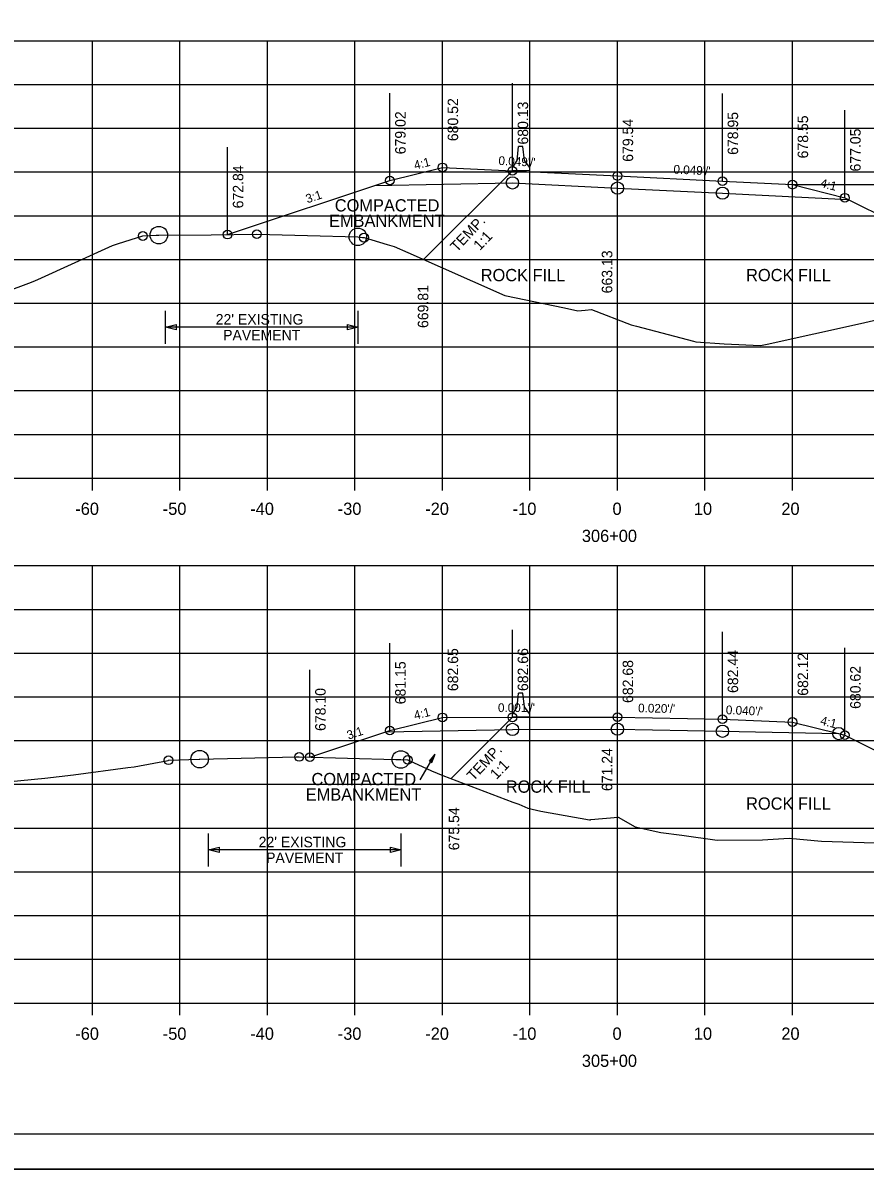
# Model space of a CAD drawing. Extents: x 1370515 to 1370849, y 383299 to 386073.
# Drawn here: x 1370609.9 to 1370706.1, y 384152.8 to 384283.8 of the extents above; entities that cross this region are included whole.
import ezdxf

# ---------------------------------------------------------------- set-up
doc = ezdxf.new("R2010")
doc.units = 0
for name, color, linetype in [('R_Alt Surface', 7, 'Continuous'), ('R_Axis', 7, 'Continuous'), ('R_Axis Annot', 7, 'Continuous'), ('R_Border', 7, 'Continuous'), ('R_Detour', 7, 'Continuous'), ('R_Exist Surface', 7, 'Continuous'), ('R_Fin Surface', 7, 'Continuous'), ('R_Grid', 7, 'Continuous'), ('R_No Plot', 7, 'Continuous'), ('R_ROW Annot', 7, 'Continuous'), ('R_Xsect Elev', 7, 'Continuous'), ('R_Xsect Slope', 7, 'Continuous')]:
    doc.layers.add(name, color=color, linetype=linetype)

msp = doc.modelspace()

# ---------------------------------------------------------------- linework, layer by layer
at = {"layer": 'R_Alt Surface'}
for points in [[(1370650.04, 384265.2), (1370665.8, 384265.51), (1370677.8, 384264.92), (1370689.8, 384264.33), (1370704.19, 384263.62)], [(1370651.34, 384202.76), (1370665.8, 384203.04), (1370677.8, 384203.06), (1370689.8, 384202.82), (1370703.09, 384202.56)]]:
    msp.add_lwpolyline(points, dxfattribs=at)
at = {"layer": 'R_Axis'}
for p, q in [((1370617.8, 384230.36), (1370617.8, 384233.16)), ((1370627.8, 384230.36), (1370627.8, 384233.16)), ((1370637.8, 384230.36), (1370637.8, 384233.16)), ((1370647.8, 384230.36), (1370647.8, 384233.16)), ((1370657.8, 384230.36), (1370657.8, 384233.16)), ((1370667.8, 384230.36), (1370667.8, 384233.16)), ((1370677.8, 384230.36), (1370677.8, 384233.16)), ((1370687.8, 384230.36), (1370687.8, 384233.16)), ((1370697.8, 384230.36), (1370697.8, 384233.16)), ((1370537.8, 384231.76), (1370817.8, 384231.76)), ((1370617.8, 384170.36), (1370617.8, 384173.16)), ((1370627.8, 384170.36), (1370627.8, 384173.16)), ((1370637.8, 384170.36), (1370637.8, 384173.16)), ((1370647.8, 384170.36), (1370647.8, 384173.16)), ((1370657.8, 384170.36), (1370657.8, 384173.16)), ((1370667.8, 384170.36), (1370667.8, 384173.16)), ((1370677.8, 384170.36), (1370677.8, 384173.16)), ((1370687.8, 384170.36), (1370687.8, 384173.16)), ((1370697.8, 384170.36), (1370697.8, 384173.16)), ((1370537.8, 384171.76), (1370817.8, 384171.76))]:
    msp.add_line(p, q, dxfattribs=at)
at = {"layer": 'R_Border'}
msp.add_line((1370843.98, 384156.76), (1370527.8, 384156.76), dxfattribs=at)
at = {"layer": 'R_Detour'}
for p, q in [((1370666.36, 384268.07), (1370666.5, 384269.65)), ((1370666.75, 384269.66), (1370666.5, 384269.65)), ((1370667, 384269.66), (1370666.75, 384269.66)), ((1370667.19, 384268.08), (1370667, 384269.66)), ((1370665.8, 384267.22), (1370666.36, 384268.07)), ((1370667.8, 384267.26), (1370667.19, 384268.08)), ((1370665.8, 384266.89), (1370655.65, 384256.74)), ((1370665.8, 384266.89), (1370665.8, 384267.22)), ((1370667.8, 384266.93), (1370665.8, 384266.89)), ((1370667.8, 384266.93), (1370667.8, 384267.26)), ((1370666.36, 384205.6), (1370666.5, 384207.18)), ((1370666.75, 384207.19), (1370666.5, 384207.18)), ((1370667, 384207.19), (1370666.75, 384207.19)), ((1370667.19, 384205.61), (1370667, 384207.19)), ((1370665.8, 384204.75), (1370666.36, 384205.6)), ((1370665.8, 384204.42), (1370665.8, 384204.75)), ((1370667.8, 384204.79), (1370667.19, 384205.61)), ((1370667.8, 384204.46), (1370667.8, 384204.79)), ((1370665.8, 384204.42), (1370658.79, 384197.41)), ((1370667.8, 384204.46), (1370665.8, 384204.42)), ((1370655.26, 384197.26), (1370656.97, 384200.19)), ((1370656.34, 384199.4), (1370656.97, 384200.19)), ((1370656.36, 384199.39), (1370656.89, 384200.04)), ((1370656.38, 384199.38), (1370656.8, 384199.9)), ((1370656.4, 384199.36), (1370656.72, 384199.75)), ((1370656.42, 384199.35), (1370656.63, 384199.61)), ((1370656.45, 384199.34), (1370656.55, 384199.46)), ((1370656.49, 384199.31), (1370656.55, 384199.46)), ((1370656.51, 384199.3), (1370656.63, 384199.61)), ((1370656.53, 384199.29), (1370656.72, 384199.75)), ((1370656.55, 384199.27), (1370656.8, 384199.9)), ((1370656.57, 384199.26), (1370656.89, 384200.04)), ((1370656.6, 384199.25), (1370656.97, 384200.19)), ((1370656.34, 384199.4), (1370656.6, 384199.25))]:
    msp.add_line(p, q, dxfattribs=at)
at = {"layer": 'R_Exist Surface'}
for points in [[(1370601.92, 384250.86), (1370610.84, 384254.16), (1370611.28, 384254.36), (1370611.57, 384254.48), (1370620.09, 384258.35), (1370620.8, 384258.58), (1370623.57, 384259.44), (1370625.08, 384259.53), (1370625.39, 384259.54), (1370631.38, 384259.58), (1370636.59, 384259.64), (1370642.37, 384259.5), (1370648.14, 384259.35), (1370648.67, 384259.27), (1370648.84, 384259.25), (1370651.5, 384258.46), (1370652.27, 384258.23), (1370653.85, 384257.54), (1370664.93, 384252.63), (1370671.77, 384251.24), (1370673.29, 384250.88), (1370674.13, 384250.96), (1370674.84, 384251.03), (1370679.36, 384249.3), (1370680, 384249.14), (1370686.48, 384247.43), (1370686.76, 384247.35), (1370690.02, 384247.13), (1370694.16, 384246.92), (1370694.92, 384247.07), (1370705.59, 384249.44), (1370714.14, 384251.41)], [(1370608.06, 384197.05), (1370612.36, 384197.45), (1370615.65, 384197.85), (1370621.84, 384198.7), (1370622.57, 384198.76), (1370626.45, 384199.5), (1370626.5, 384199.51), (1370630, 384199.63), (1370630.06, 384199.64), (1370641.1, 384199.89), (1370641.43, 384199.89), (1370652.46, 384199.61), (1370653.05, 384199.6), (1370653.8, 384199.56), (1370653.84, 384199.56), (1370654.01, 384199.49), (1370656.55, 384198.3), (1370657.84, 384197.77), (1370665.85, 384194.73), (1370666.54, 384194.48), (1370667.58, 384194.04), (1370669.05, 384193.68), (1370674.63, 384192.7), (1370674.71, 384192.7), (1370674.77, 384192.74), (1370677.87, 384193), (1370679.83, 384191.9), (1370682.75, 384191.27), (1370685.15, 384190.93), (1370689.21, 384190.39), (1370694.39, 384190.43), (1370697.44, 384190.59), (1370701.13, 384190.26), (1370707.22, 384190.06)]]:
    msp.add_lwpolyline(points, dxfattribs=at)
at = {"layer": 'R_Fin Surface'}
for points in [[(1370633.25, 384259.6), (1370651.8, 384265.78), (1370657.8, 384267.28), (1370665.8, 384266.89), (1370677.8, 384266.3), (1370689.8, 384265.71), (1370697.8, 384265.31), (1370703.8, 384263.81), (1370709.47, 384260.98), (1370733.21, 384249.11)], [(1370697.8, 384265.31), (1370702.8, 384265.31), (1370707.8, 384265.31)], [(1370642.66, 384199.86), (1370651.8, 384202.91), (1370657.8, 384204.41), (1370665.8, 384204.42), (1370677.8, 384204.44), (1370689.8, 384204.2), (1370697.8, 384203.88), (1370703.09, 384202.56), (1370703.8, 384202.38), (1370732.04, 384188.26), (1370739.04, 384188.26), (1370744.9, 384190.22)]]:
    msp.add_lwpolyline(points, dxfattribs=at)
at = {"layer": 'R_Grid'}
for p, q in [((1370537.8, 384281.76), (1370817.8, 384281.76)), ((1370617.8, 384231.76), (1370617.8, 384281.76)), ((1370627.8, 384231.76), (1370627.8, 384281.76)), ((1370637.8, 384231.76), (1370637.8, 384281.76)), ((1370647.8, 384231.76), (1370647.8, 384281.76)), ((1370657.8, 384231.76), (1370657.8, 384281.76)), ((1370667.8, 384231.76), (1370667.8, 384281.76)), ((1370677.8, 384231.76), (1370677.8, 384281.76)), ((1370687.8, 384231.76), (1370687.8, 384281.76)), ((1370697.8, 384231.76), (1370697.8, 384281.76)), ((1370537.8, 384276.76), (1370817.8, 384276.76)), ((1370537.8, 384271.76), (1370817.8, 384271.76)), ((1370537.8, 384266.76), (1370817.8, 384266.76)), ((1370537.8, 384261.76), (1370817.8, 384261.76)), ((1370537.8, 384256.76), (1370817.8, 384256.76)), ((1370537.8, 384251.76), (1370817.8, 384251.76)), ((1370537.8, 384246.76), (1370817.8, 384246.76)), ((1370537.8, 384241.76), (1370817.8, 384241.76)), ((1370537.8, 384236.76), (1370817.8, 384236.76)), ((1370537.8, 384231.76), (1370817.8, 384231.76)), ((1370537.8, 384221.76), (1370817.8, 384221.76)), ((1370617.8, 384171.76), (1370617.8, 384221.76)), ((1370627.8, 384171.76), (1370627.8, 384221.76)), ((1370637.8, 384171.76), (1370637.8, 384221.76)), ((1370647.8, 384171.76), (1370647.8, 384221.76)), ((1370657.8, 384171.76), (1370657.8, 384221.76)), ((1370667.8, 384171.76), (1370667.8, 384221.76)), ((1370677.8, 384171.76), (1370677.8, 384221.76)), ((1370687.8, 384171.76), (1370687.8, 384221.76)), ((1370697.8, 384171.76), (1370697.8, 384221.76)), ((1370537.8, 384216.76), (1370817.8, 384216.76)), ((1370537.8, 384211.76), (1370817.8, 384211.76)), ((1370537.8, 384206.76), (1370817.8, 384206.76)), ((1370537.8, 384201.76), (1370817.8, 384201.76)), ((1370537.8, 384196.76), (1370817.8, 384196.76)), ((1370537.8, 384191.76), (1370817.8, 384191.76)), ((1370537.8, 384186.76), (1370817.8, 384186.76)), ((1370537.8, 384181.76), (1370817.8, 384181.76)), ((1370537.8, 384176.76), (1370817.8, 384176.76)), ((1370537.8, 384171.76), (1370817.8, 384171.76))]:
    msp.add_line(p, q, dxfattribs=at)
at = {"layer": 'R_No Plot'}
msp.add_line((1370515.4, 384152.78), (1370848.73, 384152.78), dxfattribs=at)
for points in [[(1370515.39, 384366.12), (1370848.73, 384366.12), (1370848.73, 384152.78), (1370515.39, 384152.78)], [(1370761.72, 384362.22), (1370761.72, 384352.34), (1370797.45, 384352.34), (1370797.45, 384349.42), (1370820.65, 384349.42), (1370820.65, 384326.21), (1370843.98, 384326.21), (1370843.98, 384156.76), (1370527.8, 384156.76), (1370527.8, 384362.22)]]:
    msp.add_lwpolyline(points, close=True, dxfattribs=at)
for centre, radius in [((1370657.8, 384267.28), 0.5), ((1370651.8, 384265.78), 0.5), ((1370651.8, 384265.78), 0.5), ((1370665.8, 384266.89), 0.5), ((1370677.8, 384266.3), 0.5), ((1370665.8, 384265.51), 0.7), ((1370677.8, 384264.92), 0.7), ((1370677.8, 384264.92), 0.7), ((1370689.8, 384264.33), 0.7), ((1370689.8, 384265.71), 0.5), ((1370697.8, 384265.31), 0.5), ((1370703.8, 384263.81), 0.5), ((1370703.8, 384263.81), 0.5), ((1370623.57, 384259.44), 0.5), ((1370625.39, 384259.54), 1), ((1370633.25, 384259.6), 0.5), ((1370636.59, 384259.64), 0.5), ((1370648.14, 384259.35), 1), ((1370648.84, 384259.25), 0.5), ((1370657.8, 384204.41), 0.5), ((1370665.8, 384204.42), 0.5), ((1370677.8, 384204.44), 0.5), ((1370689.8, 384204.2), 0.5), ((1370651.8, 384202.91), 0.5), ((1370651.8, 384202.91), 0.5), ((1370665.8, 384203.04), 0.7), ((1370677.8, 384203.06), 0.7), ((1370677.8, 384203.06), 0.7), ((1370689.8, 384202.82), 0.7), ((1370697.8, 384203.88), 0.5), ((1370703.09, 384202.56), 0.7), ((1370703.8, 384202.38), 0.5), ((1370703.8, 384202.38), 0.5), ((1370626.5, 384199.51), 0.5), ((1370630.06, 384199.64), 1), ((1370641.43, 384199.89), 0.5), ((1370642.66, 384199.86), 0.5), ((1370653.05, 384199.6), 1), ((1370653.84, 384199.56), 0.5)]:
    msp.add_circle(centre, radius, dxfattribs=at)
at = {"layer": 'R_ROW Annot'}
for p, q in [((1370626.16, 384247.13), (1370626.16, 384250.9)), ((1370648.16, 384247.13), (1370648.16, 384250.9)), ((1370648.16, 384249.01), (1370626.16, 384249.01)), ((1370631.07, 384187.38), (1370631.07, 384191.14)), ((1370653.07, 384187.38), (1370653.07, 384191.14)), ((1370653.07, 384189.26), (1370631.07, 384189.26))]:
    msp.add_line(p, q, dxfattribs=at)
for points in [[(1370627.36, 384248.71), (1370626.16, 384249.01), (1370627.36, 384249.31)], [(1370646.96, 384249.31), (1370648.16, 384249.01), (1370646.96, 384248.71)], [(1370632.27, 384188.96), (1370631.07, 384189.26), (1370632.27, 384189.56)], [(1370651.87, 384189.56), (1370653.07, 384189.26), (1370651.87, 384188.96)]]:
    msp.add_lwpolyline(points, close=True, dxfattribs=at)
at = {"layer": 'R_Xsect Elev'}
for p, q in [((1370657.8, 384267.28), (1370657.8, 384277.28)), ((1370665.8, 384266.89), (1370665.8, 384276.89)), ((1370651.8, 384265.78), (1370651.8, 384275.78)), ((1370689.8, 384265.71), (1370689.8, 384275.71)), ((1370677.8, 384264.92), (1370677.8, 384274.92)), ((1370697.8, 384265.31), (1370697.8, 384275.31)), ((1370703.8, 384263.81), (1370703.8, 384273.81)), ((1370633.25, 384259.6), (1370633.25, 384269.6)), ((1370677.82, 384249.88), (1370677.82, 384259.88)), ((1370657.8, 384204.41), (1370657.8, 384214.41)), ((1370665.8, 384204.42), (1370665.8, 384214.42)), ((1370689.8, 384204.2), (1370689.8, 384214.2)), ((1370697.8, 384203.88), (1370697.8, 384213.88)), ((1370651.8, 384202.91), (1370651.8, 384212.91)), ((1370677.8, 384203.06), (1370677.8, 384213.06)), ((1370703.8, 384202.38), (1370703.8, 384212.38)), ((1370642.66, 384199.86), (1370642.66, 384209.86)), ((1370677.82, 384192.99), (1370677.82, 384202.99))]:
    msp.add_line(p, q, dxfattribs=at)

# ---------------------------------------------------------------- texts
at = {"layer": 'R_Axis Annot'}
for s, p in [('COMPACTED', (1370645.5, 384262.24)), ('EMBANKMENT', (1370644.84, 384260.48)), ('ROCK FILL', (1370662.18, 384254.27)), ('ROCK FILL', (1370692.51, 384254.27)), ('-60', (1370615.84, 384227.56)), ('-50', (1370625.84, 384227.56)), ('-40', (1370635.84, 384227.56)), ('-30', (1370645.84, 384227.56)), ('-20', (1370655.84, 384227.56)), ('-10', (1370665.84, 384227.56)), ('0', (1370677.24, 384227.56)), ('10', (1370686.54, 384227.56)), ('20', (1370696.54, 384227.56)), ('306+00', (1370673.74, 384224.46)), ('COMPACTED', (1370642.84, 384196.66)), ('ROCK FILL', (1370665.05, 384195.8)), ('EMBANKMENT', (1370642.18, 384194.9)), ('ROCK FILL', (1370692.51, 384193.86)), ('-60', (1370615.84, 384167.56)), ('-50', (1370625.84, 384167.56)), ('-40', (1370635.84, 384167.56)), ('-30', (1370645.84, 384167.56)), ('-20', (1370655.84, 384167.56)), ('-10', (1370665.84, 384167.56)), ('0', (1370677.24, 384167.56)), ('10', (1370686.54, 384167.56)), ('20', (1370696.54, 384167.56)), ('305+00', (1370673.74, 384164.46))]:
    msp.add_text(s, height=1.4, dxfattribs=at).set_placement(p)
at = {"layer": 'R_Detour'}
for s, p in [('TEMP.', (1370659.45, 384257.53)), ('1:1', (1370662.08, 384257.7)), ('TEMP.', (1370661.35, 384197.07)), ('1:1', (1370663.99, 384197.24))]:
    msp.add_text(s, height=1.2, rotation=46.5651, dxfattribs=at).set_placement(p)
at = {"layer": 'R_No Plot'}
for p in [(1370620.05, 384258.3), (1370652.23, 384258.18), (1370611.24, 384254.31), (1370664.88, 384252.58), (1370673.25, 384250.83), (1370674.8, 384250.98), (1370679.96, 384249.09), (1370686.72, 384247.3), (1370694.11, 384246.87), (1370622.52, 384198.71), (1370656.5, 384198.25), (1370615.6, 384197.8), (1370666.5, 384194.43), (1370677.83, 384192.95), (1370674.59, 384192.65), (1370682.71, 384191.22), (1370689.17, 384190.34), (1370697.39, 384190.54)]:
    msp.add_text('+', height=0.1, dxfattribs=at).set_placement(p)
at = {"layer": 'R_ROW Annot'}
for s, p in [("22' EXISTING", (1370631.89, 384249.31)), ('PAVEMENT', (1370632.74, 384247.51)), ("22' EXISTING", (1370636.8, 384189.56)), ('PAVEMENT', (1370637.65, 384187.76))]:
    msp.add_text(s, height=1.2, dxfattribs=at).set_placement(p)
at = {"layer": 'R_Xsect Elev'}
for s, p in [('680.52', (1370659.6, 384270.28)), ('680.13', (1370667.6, 384269.89)), ('679.02', (1370653.6, 384268.78)), ('678.95', (1370691.6, 384268.71)), ('678.55', (1370699.6, 384268.31)), ('679.54', (1370679.6, 384267.92)), ('677.05', (1370705.6, 384266.81)), ('672.84', (1370635.05, 384262.6)), ('663.13', (1370677.22, 384252.88)), ('669.81', (1370656.19, 384248.92)), ('682.65', (1370659.6, 384207.41)), ('682.66', (1370667.6, 384207.42)), ('682.44', (1370691.6, 384207.2)), ('682.12', (1370699.6, 384206.88)), ('681.15', (1370653.6, 384205.91)), ('682.68', (1370679.6, 384206.06)), ('680.62', (1370705.6, 384205.38)), ('678.10', (1370644.46, 384202.86)), ('671.24', (1370677.22, 384195.99)), ('675.54', (1370659.72, 384189.22))]:
    msp.add_text(s, height=1.2, rotation=90, dxfattribs=at).set_placement(p)
at = {"layer": 'R_Xsect Slope'}
for s, rotation, p in [('4:1', 14.0362, (1370654.68, 384267.02)), ("0.049'/'", 357.1801, (1370664.19, 384267.57)), ("0.049'/'", 357.1801, (1370684.19, 384266.58)), ('4:1', 345.9638, (1370700.92, 384265.05)), ('3:1', 18.4349, (1370642.37, 384263.17)), ("0.001'/'", 0.0853, (1370664.15, 384205.02)), ("0.020'/'", 358.8542, (1370680.16, 384204.99)), ('4:1', 14.0362, (1370654.68, 384204.14)), ("0.040'/'", 357.7094, (1370690.18, 384204.78)), ('4:1', 345.9638, (1370700.92, 384203.61)), ('3:1', 18.4349, (1370647.07, 384201.86))]:
    msp.add_text(s, height=1, rotation=rotation, dxfattribs=at).set_placement(p)

doc.saveas('drawing.dxf')
